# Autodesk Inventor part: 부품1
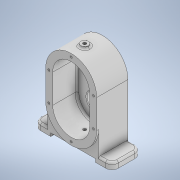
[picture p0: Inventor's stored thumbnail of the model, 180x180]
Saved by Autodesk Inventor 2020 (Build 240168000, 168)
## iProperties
Created: 2021-05
Part Number: 부품1
Material: 일반
Document SubType Name: Modeling
Designer: Owner
Density: 1 g/cm^3
Appearance: 기본값
Author: Owner
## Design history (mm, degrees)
sketch "스케치1"
  geometry: L1 (0, 22.5)-(0, -22.5); L2 (-40, 22.5)-(-40, -22.5); L3 (40, -22.5)-(40, 22.5); A1 r 40 centre (0, 22.5) between (40, 22.5) and (-40, 22.5); A2 r 40 centre (0, -22.5) between (-40, -22.5) and (40, -22.5); 2 further points
  constraints: 8 end point, 4 point on circle, 4 tangent, 2 centre point, 1 coincident, 1 midpoint, 1 parallel, 1 vertical
  dimensions: "d0" = 80 distance between parallel lines of L3 L2; "d1" = 45 distance of L1.end L1.start
extrude "돌출1" new body sketch "스케치1" distance "d2" = 49; taper "d3" = 0 deg
feature "쉘2" dims "d10" = 11
sketch "스케치3"
  geometry: L1 (-40, -22.5)-(-40, 22.5) reference; L2 (-40, 0)-(-40, -59.5); L3 (-40, -59.5)-(-61, -59.5); L4 (-61, -59.5)-(-61, -69.5); L5 (-61, -69.5)-(-35, -69.5); L6 (-35, -69.5)-(-35, -64.5); L7 (-35, -64.5)-(35, -64.5); L8 (35, -64.5)-(35, -69.5); L9 (35, -69.5)-(61, -69.5); L10 (61, -69.5)-(61, -59.5); L11 (61, -59.5)-(40, -59.5); L12 (40, -59.5)-(40, -14.556); L13 (40, 22.5)-(40, -22.5) reference; L14 (0, -104.56)-(0, 90.343) reference; A1 r 40 centre (0, -22.5) between (-40, -22.5) and (40, -22.5) reference; 3 further points
  constraints: 22 end point, 7 perpendicular, 3 point on line, 3 vertical, 1 midpoint, 1 parallel, 3 other
  dimensions: "d11" = 10 distance of L3.end L4.end; "d12" = 122 distance between parallel lines of L10 L4; "d13" = 47 distance from line of L5 L1.start; "d61" = 70 distance between parallel lines of L6 L8; "d62" = 5 distance of L7.end L8.end
extrude "돌출3" join sketch "스케치3" distance "d14" = 46; taper "d15" = 0 deg
sketch "스케치6"
  geometry: L1 (0, 22.5)-(0, -22.5); L2 (-26, 22.5)-(-26, -22.5); L3 (26, -22.5)-(26, 22.5); A1 r 26 centre (0, 22.5) between (26, 22.5) and (-26, 22.5); A2 r 26 centre (0, -22.5) between (-26, -22.5) and (26, -22.5); 2 further points
  constraints: 8 end point, 4 point on circle, 4 tangent, 2 centre point, 1 coincident, 1 midpoint, 1 parallel, 1 vertical
  dimensions: "d19" = 52 distance between parallel lines of L2 L3; "d20" = 45 distance of L1.end L1.start
extrude "돌출4" join sketch "스케치6" distance "d21" = 7; taper "d22" = 0 deg
sketch "스케치7"
  geometry: L1 (0, 22.5)-(0, -22.5); L2 (-26, -7.5)-(-26, -22.5); L3 (26, -22.5)-(26, -7.5); L4 (-26, -7.5)-(26, -7.5); L5 (-61, -69.5)-(-35, -69.5) reference; A1 r 26 centre (0, -22.5) between (-26, -22.5) and (26, -22.5); 2 further points
  constraints: 10 end point, 2 point on circle, 2 tangent, 1 centre point, 1 coincident, 1 midpoint, 1 parallel, 1 perpendicular, 1 vertical, 1 other
  dimensions: "d24" = 30 distance from line of L4 L1.start; "d25" = 52 distance between parallel lines of L3 L2; "d26" = 62 distance between parallel lines of L5 L4
extrude "돌출5" join sketch "스케치7" distance "d27" = 3; taper "d28" = 0 deg
sketch "스케치8"
  geometry: L1 (22.5, 0)-(22.5, 49) reference; L2 (22.5, 32.035)-(22.5, -31.501); L3 (51.5, 11)-(22.5, 11) reference; L4 (36.5, 11)-(36.5, 0); L5 (36.5, 0)-(33.5, 0); L6 (33.5, 0)-(33.5, -4); L7 (33.5, -4)-(36.5, -4); L8 (62.5, 0)-(22.5, 0) reference; L9 (36.5, -4)-(36.5, -7); L10 (22.5, -7)-(48.5, -7) reference; L11 (36.5, -7)-(22.5, -7); 2 further points
  constraints: 14 end point, 3 collinear, 3 point on line, 2 vertical, 1 horizontal, 1 parallel, 1 perpendicular
  dimensions: "d29" = 22 diameter of L6 L1; "d30" = 28 diameter of L9 L2; "d31" = 4 distance of L5.end L6.end; "d32" = 3 distance of L7.end L9.end
revolve "회전1" sketch "스케치8" stored, may be unused: angle "d33" = 90 deg
sketch "스케치9"
  geometry: L1 (-22.5, 11)-(-22.5, 49) reference; L2 (-22.5, 39.78)-(-22.5, -27.628); L3 (22.5, 11)-(-22.5, 11) reference; L4 (-8.5, 11)-(-8.5, 0); L5 (-8.5, 0)-(-12.5, 0); L6 (-12.5, 0)-(-12.5, -4); L7 (-12.5, -4)-(-22.5, -4); 2 further points
  constraints: 10 end point, 3 perpendicular, 3 point on line, 1 collinear, 1 vertical
  dimensions: "d34" = 28 diameter of L4 L2; "d35" = 20 diameter of L6 L2; "d36" = 4 distance of L5.end L6.end; "d37" = 11 distance of L4.start L4.end
revolve "회전2" sketch "스케치9" stored, may be unused: angle "d38" = 90 deg
node "작업 평면2"
sketch "스케치10"
  geometry: L1 (40, 49)-(-40, 49) reference; L2 (0, 28)-(0, 0); C1 r 6 at (0, 28)
  constraints: 2 end point, 1 centre point, 1 vertical
  dimensions: "d41" = 21 distance from line of L2.start L1; "d42" = 12 diameter of C1
extrude "돌출6" join sketch "스케치10" stored distance "d43" = 3; taper "d44" = 0 deg
sketch "스케치11"
  geometry: C1 r 6 at (0, 0) reference; 2 further points
  constraints: 1 coincident
hole "구멍1" sketch "스케치11" at (0, 0) diameter "d45" = 4.917; stored, may be unused: countersink angle "d49" = 90 deg, drill point angle "d51" = 0 deg; dims "d46" = 17, "d47" = 4, "d48" = 2, "d50" = 17.1
sketch "스케치12"
  geometry: L1 (0, 22.5)-(0, -22.5); L2 (-35, 22.5)-(-35, -22.5); L3 (35, -22.5)-(35, 22.5); A1 r 35 centre (0, 22.5) between (35, 22.5) and (-35, 22.5); A2 r 35 centre (0, -22.5) between (-35, -22.5) and (35, -22.5); 8 further points
  constraints: 8 end point, 7 point on circle, 4 coincident, 4 tangent, 2 centre point, 1 midpoint, 1 parallel, 1 point on line, 1 vertical
  dimensions: "d52" = 35 radius of A1; "d53" = 45 distance of L3.start L3.end
hole "구멍2" sketch "스케치12" at (-35, 22.5), (35, -22.5), (-35, -22.5), (0, -57.5), (0, 57.5), (35, 22.5) diameter "d54" = 3.242; stored, may be unused: countersink angle "d58" = 90 deg, drill point angle "d60" = 118 deg; dims "d55" = 8, "d56" = 4, "d57" = 2, "d59" = 10
fillet "모깎기1" dims "d63" = 10
sketch "스케치13"
  geometry: 1 further point
sketch "스케치14"
  geometry: L1 (75, 49)-(-5, 49) reference; L2 (70, 0)-(70, 46) reference; 2 further points
  dimensions: "d64" = 21 distance from line of L1 point (35, 28); "d65" = 35 distance from line of point (35, 28) L2
hole "구멍3" sketch "스케치14" at (35, 28) diameter "d66" = 4.917; stored, may be unused: countersink angle "d70" = 90 deg, drill point angle "d72" = 118 deg; dims "d67" = 12, "d68" = 12, "d69" = 1, "d71" = 17.1
sketch "스케치15" dims "d73" = 40
  geometry: C1 r 11 at (0, 22.5) reference; 3 further points
  constraints: 1 coincident, 1 vertical alignment, 2 other
hole "구멍4" sketch "스케치15" at (0, 42.5) diameter "d74" = 3.242; stored, may be unused: countersink angle "d78" = 90 deg, drill point angle "d80" = 118 deg; dims "d75" = 8, "d76" = 12, "d77" = 1, "d79" = 10
chamfer "모따기1" distance "d84" = 1; stored, may be unused: second distance "d85" = 2, angle "d86" = 45 deg
fillet "모깎기2" dims "d87" = 3
fillet "모깎기3" dims "d88" = 3
fillet "모깎기4" dims "d89" = 3
chamfer "모따기2" distance "d90" = 1; stored, may be unused: second distance "d91" = 2, angle "d92" = 45 deg
node "솔리드1"
pattern_circular "원형 패턴1" dims angle "d82" = 360 deg
feature "A9D066F2-1C7D-4E18-AEED-F7BC21143FA4" dims "d54" = 3.242, "d55" = 8, "d56" = 4, "d57" = 2, "d58" = 90 deg, "d59" = 10, "d60" = 118 deg
other parameters: "d40" = 65.5
